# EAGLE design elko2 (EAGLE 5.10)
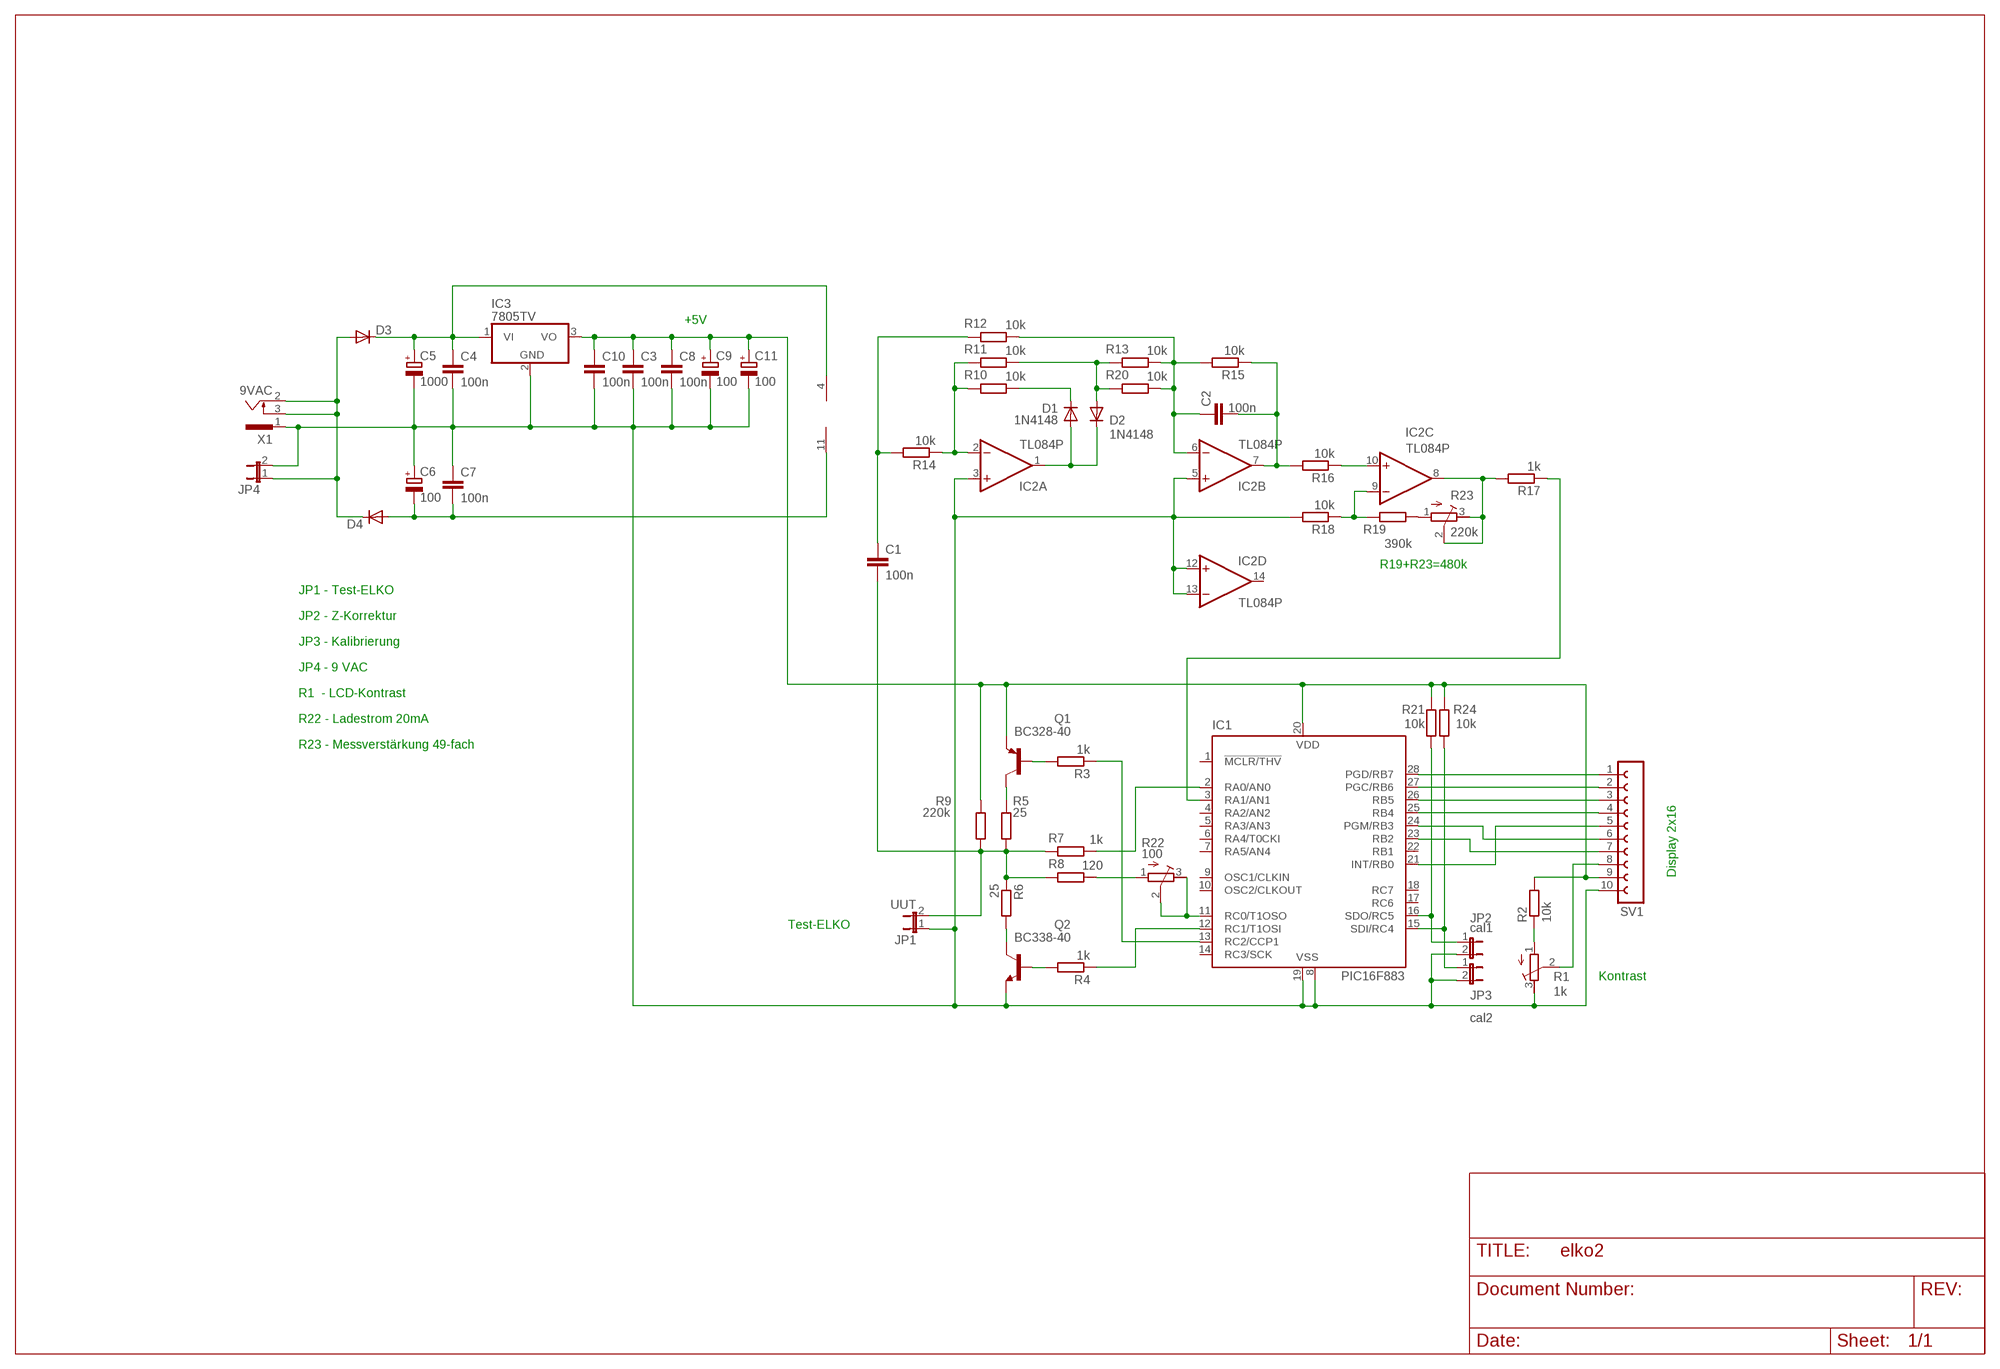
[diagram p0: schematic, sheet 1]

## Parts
C1  100n  C-EU050-025X075  [C050-025X075]
C2  100n  C-EU050-025X075  [C050-025X075]
C3  100n  C-EU050-025X075  [C050-025X075]
C4  100n  C-EU050-025X075  [C050-025X075]
C5  1000  CPOL-EUE5-8.5  [E5-8,5]
C6  100  CPOL-EUE5-6  [E5-6]
C7  100n  C-EU050-025X075  [C050-025X075]
C8  100n  C-EU050-025X075  [C050-025X075]
C9  100  CPOL-EUE5-6  [E5-6]
C10  100n  C-EU050-025X075  [C050-025X075]
C11  100  CPOL-EUE5-6  [E5-6]
D1  1N4148  1N4148DO35-7  [DO35-7]
D2  1N4148  1N4148DO35-7  [DO35-7]
D3  DIODE-DO15-12  [DO15-12]
D4  DIODE-DO15-12  [DO15-12]
IC1  PIC16F883  PIC16873P  [DIL28-3]
IC2  TL084P  [DIL14]
IC3  7805TV  [TO220V]
JP1  UUT  JP1E  [JP1]
JP2  cal1  JP1E  [JP1]
JP3  cal2  JP1E  [JP1]
JP4  JP1E  [JP1]
Q1  BC328-40  [TO92-EBC]
Q2  BC338-40  [TO92-EBC]
R1  1k  R-TRIMM3339P  [RTRIM3339P]
R2  10k  R-EU_0207/10  [0207/10]
R3  1k  R-EU_0207/10  [0207/10]
R4  1k  R-EU_0207/10  [0207/10]
R5  25  R-EU_0207/10  [0207/10]
R6  25  R-EU_0207/10  [0207/10]
R7  1k  R-EU_0207/10  [0207/10]
R8  120  R-EU_0207/10  [0207/10]
R9  220k  R-EU_0207/10  [0207/10]
R10  10k  R-EU_0207/10  [0207/10]
R11  10k  R-EU_0207/10  [0207/10]
R12  10k  R-EU_0207/10  [0207/10]
R13  10k  R-EU_0207/10  [0207/10]
R14  10k  R-EU_0207/10  [0207/10]
R15  10k  R-EU_0207/10  [0207/10]
R16  10k  R-EU_0207/10  [0207/10]
R17  1k  R-EU_0207/10  [0207/10]
R18  10k  R-EU_0207/10  [0207/10]
R19  390k  R-EU_0207/10  [0207/10]
R20  10k  R-EU_0207/10  [0207/10]
R21  10k  R-EU_0207/10  [0207/10]
R22  100  R-TRIMM64W  [RTRIM64W]
R23  220k  R-TRIMM64W  [RTRIM64W]
R24  10k  R-EU_0207/10  [0207/10]
SV1  FE10-1  [FE10]
X1  9VAC  733989-5  [733989-5]

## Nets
N$1: IC1.28(PGD/RB7) SV1.1
N$2: IC1.27(PGC/RB6) SV1.2
N$3: IC1.26(RB5) SV1.3
N$4: IC1.25(RB4) SV1.4
N$5: IC1.21(INT/RB0) SV1.5
N$6: IC1.24(PGM/RB3) SV1.6
N$7: IC1.23(RB2) SV1.7
N$8: R19.1 R23.1(E)
N$9: R8.1 R22.1(E)
N$10: C3.1 C8.1 C9.+ C10.1 C11.+ IC1.20(VDD) IC3.3(VO) Q1.E R2.2 R9.1 R21.2 R24.2 SV1.9
N$11: R1.2(S) SV1.8
N$12: C1.2 JP1.2 R5.2 R6.1 R7.2 R8.2 R9.2
N$13: IC1.2(RA0/AN0) R7.1
N$14: IC1.11(RC0/T1OSO) R22.2(S) R22.3(A)
N$15: Q1.C R5.1
N$16: Q1.B R3.2
N$17: Q2.B R4.2
N$18: IC1.12(RC1/T1OSI) R4.1
N$19: IC1.13(RC2/CCP1) R3.1
N$20: C4.1 C5.+ D3.C IC2.4(P:V+) IC3.1(VI)
N$21: IC2.2(A:-IN) R10.2 R11.2 R14.1
N$22: D1.A D2.C IC2.1(A:OUT)
N$23: R1.1(E) R2.1
N$24: D1.C R10.1
N$25: D2.A R11.1 R13.2 R20.2
N$26: C1.1 R12.2 R14.2
N$27: C2.1 IC2.6(B:-IN) R12.1 R13.1 R15.2 R20.1
N$28: IC1.16(SDO/RC5) JP2.1 R21.1
N$29: C2.2 IC2.7(B:OUT) R15.1 R16.2
N$30: IC2.10(C:+IN) R16.1
N$31: IC2.8(C:OUT) R17.2 R23.2(S) R23.3(A)
N$32: IC2.9(C:-IN) R18.1 R19.2
N$33: IC1.3(RA1/AN1) R17.1
N$34: Q2.C R6.2
N$35: IC1.15(SDI/RC4) JP3.1 R24.1
N$37: C6.- C7.2 D4.A IC2.11(P:V-)
N$38: D3.A D4.C JP4.1 X1.2 X1.3
VSS: C3.2 C4.2 C5.- C6.+ C7.1 C8.2 C9.- C10.2 C11.- IC1.8(VSS) IC1.19(VSS) IC2.3(A:+IN) IC2.5(B:+IN) IC2.12(D:+IN) IC2.13(D:-IN) IC3.2(GND) JP1.1 JP2.2 JP3.2 JP4.2 Q2.E R1.3(A) R18.2 SV1.10 X1.1
Unconnected: IC1.1(!MCLR/THV) IC1.4(RA2/AN2) IC1.5(RA3/AN3) IC1.6(RA4/T0CKI) IC1.7(RA5/AN4) IC1.9(OSC1/CLKIN) IC1.10(OSC2/CLKOUT) IC1.14(RC3/SCK) IC1.17(RC6) IC1.18(RC7) IC1.22(RB1) IC2.14(D:OUT)

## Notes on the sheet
- +5V
- R19+R23=480k
- JP1 - Test-ELKO
- JP2 - Z-Korrektur
- JP3 - Kalibrierung
- JP4 - 9 VAC
- R1  - LCD-Kontrast
- R22 - Ladestrom 20mA
- R23 - Messverstärkung 49-fach
- Display 2x16
- Test-ELKO
- Kontrast

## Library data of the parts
C1-C4 C7 C8 C10 = rcl:C-EU: CAPACITOR, European symbol
C5 C6 C9 C11 = rcl:CPOL-EU: POLARIZED CAPACITOR, European symbol
D1 D2 = diode:1N4148: DIODE
D3 D4 = diode:DIODE-: DIODE
IC1 = microchip-6:PIC16*873: MICROCONTROLLER flash type
IC2 = linear:TL084: OP AMP
IC3 = linear:78*: Positive VOLTAGE REGULATOR Source: http://cache.national.com/ds/LM/LM78L05.pdf http://www.fairchildsemi.com/ds/LM/LM7805.pdf
JP1-JP4 = jumper:JP1E: JUMPER
Q1 = transistor-pnp:BC328*: PNP Transistror
Q2 = transistor-npn:BC338*: NPN Transistor
R1 R22 R23 = rcl:R-TRIMM: Trimm resistor
R2-R21 R24 = rcl:R-EU_: RESISTOR, European symbol
SV1 = con-lsta:FE10-1: FEMALE HEADER
X1 = con-conrad:73398?: FEMALE PRINT CONNECTOR Niedervolt-Steckverbinder Distributor Conrad

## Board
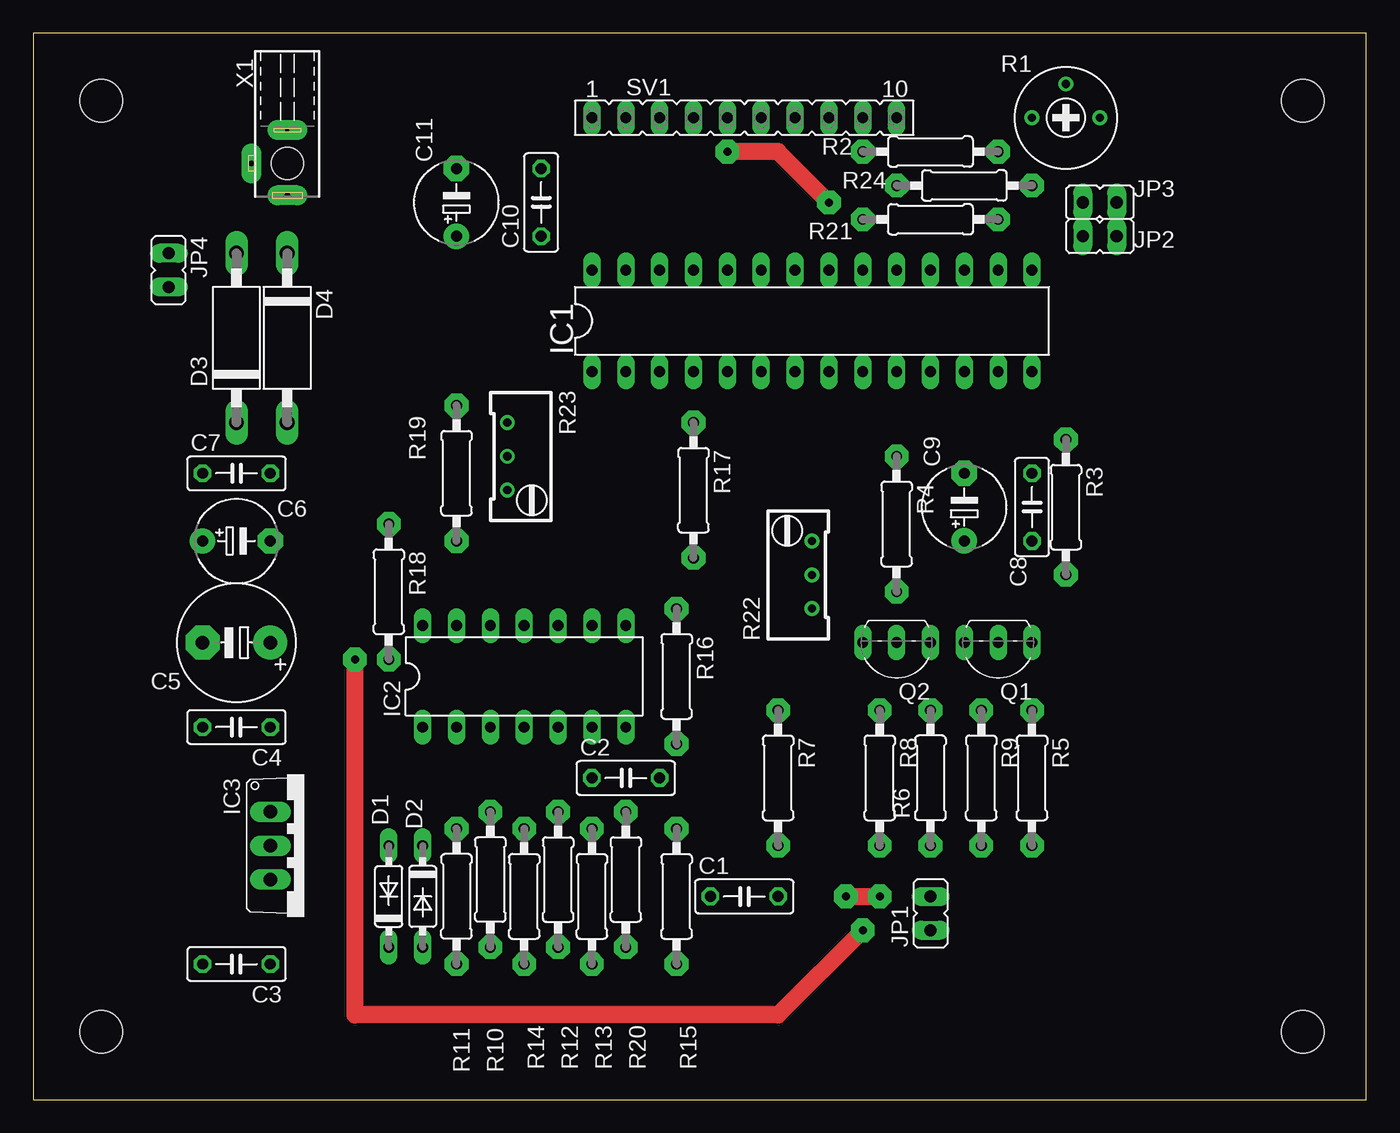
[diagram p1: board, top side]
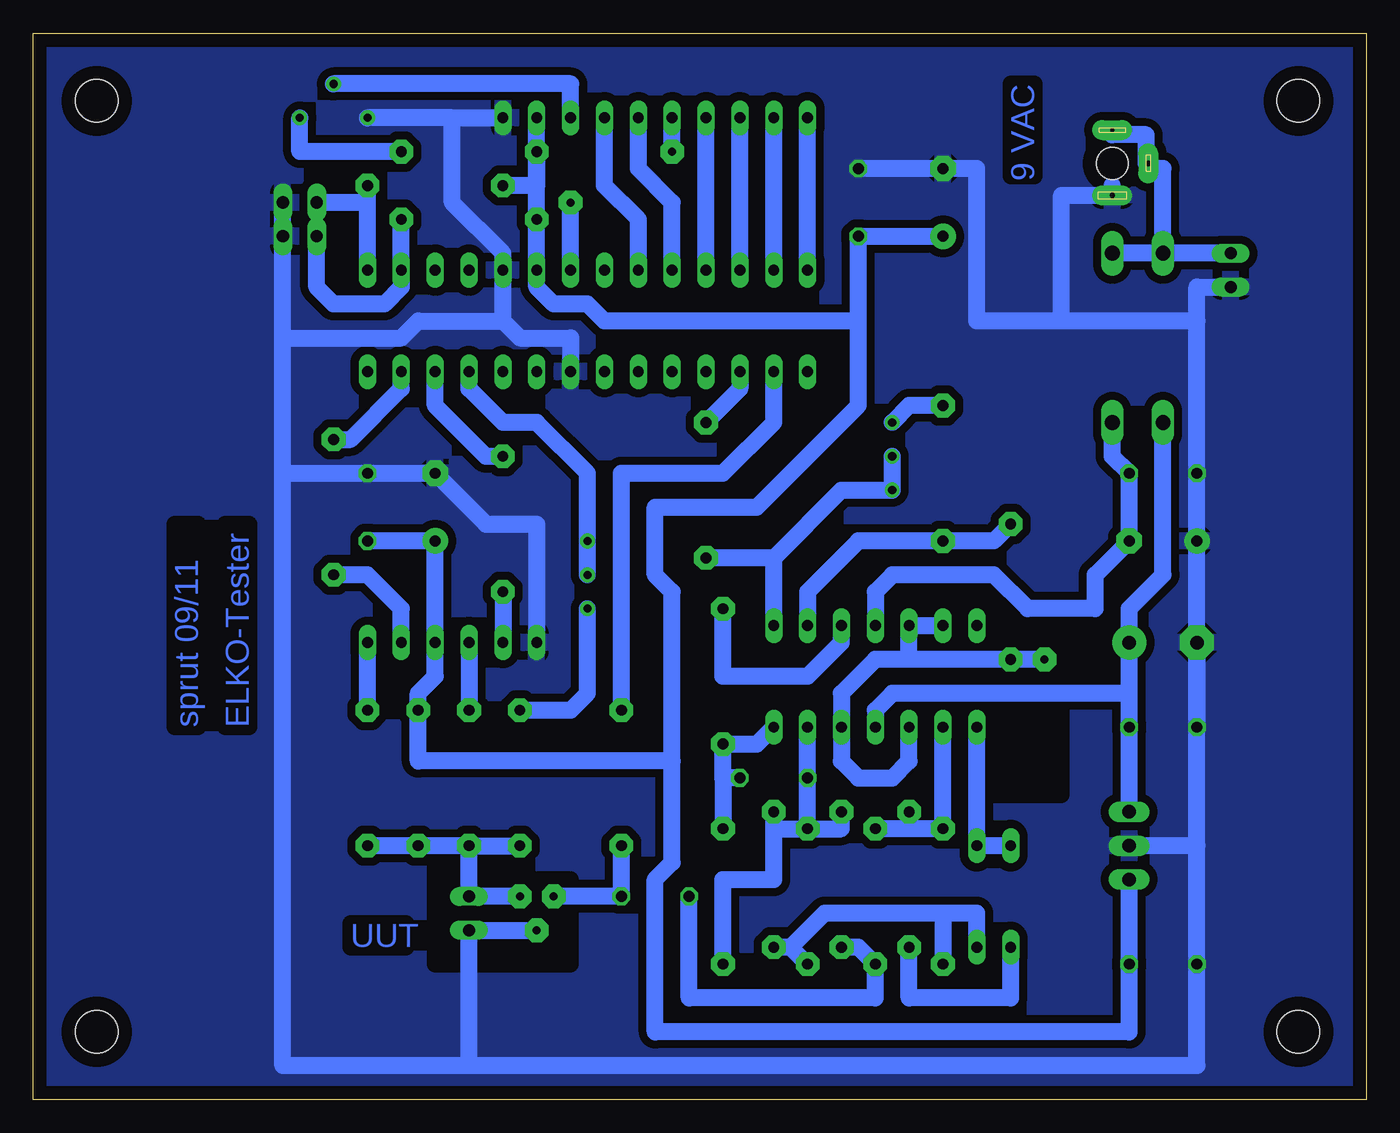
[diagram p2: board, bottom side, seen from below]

Size 100 x 80 mm. Coordinates in mm from the lower left corner, seen from the top.
Outline: 0,0 100,0 100,80 0,80 0,0
Copper layers (1*16): Top 0.035mm / dielectric 1.5mm / Bottom 0.035mm
Design rules "default": minimum track width 10mil, minimum drill 24mil, track to track 8mil, track to pad 8mil, pad to pad 8mil, via to via 8mil, smd to smd 8mil, copper to edge 40mil, drill to drill 8mil, minimum pad ring 10mil, minimum via ring 8mil, stop-mask expansion 4mil, vias tented up to drill 0mil, thermal gap 10mil
Holes 3.2 mm at 5.08,74.93 95.25,74.93 5.08,5.08 95.25,5.08
bRestrict: area 59.7,10.2 to 69.8,16.5; area 22.9,22.9 to 41.9,36.8

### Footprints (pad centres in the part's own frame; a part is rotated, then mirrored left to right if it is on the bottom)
C050-025X075 = drill 0.813 octagon: 1 -2.54,0; 2 2.54,0
E5-8,5 = drill 1.016 pad 2.54 round: + -2.54,0 | drill 1.016 pad 2.54 octagon: - 2.54,0
E5-6 = drill 0.813 pad 1.905 round: + -2.54,0 | drill 0.813 pad 1.905 octagon: - 2.54,0
DO35-7 = drill 0.813 long: A 3.81,0; C -3.81,0
DO15-12 = drill 1.118 long: A 6.35,0; C -6.35,0
DIL28-3 = drill 0.813 long: 1 -16.51,-3.81; 2 -13.97,-3.81; 3 -11.43,-3.81; 4 -8.89,-3.81; 5 -6.35,-3.81; 6 -3.81,-3.81; 7 -1.27,-3.81; 8 1.27,-3.81; 9 3.81,-3.81; 10 6.35,-3.81; 11 8.89,-3.81; 12 11.43,-3.81; 13 13.97,-3.81; 14 16.51,-3.81; 15 16.51,3.81; 16 13.97,3.81; 17 11.43,3.81; 18 8.89,3.81; 19 6.35,3.81; 20 3.81,3.81; 21 1.27,3.81; 22 -1.27,3.81; 23 -3.81,3.81; 24 -6.35,3.81; 25 -8.89,3.81; 26 -11.43,3.81; 27 -13.97,3.81; 28 -16.51,3.81
DIL14 = drill 0.813 long: 1 -7.62,-3.81; 2 -5.08,-3.81; 3 -2.54,-3.81; 4 0,-3.81; 5 2.54,-3.81; 6 5.08,-3.81; 7 7.62,-3.81; 8 7.62,3.81; 9 5.08,3.81; 10 2.54,3.81; 11 0,3.81; 12 -2.54,3.81; 13 -5.08,3.81; 14 -7.62,3.81
TO220V = drill 1.016 long: 1 -2.54,-2.54; 2 0,-2.54; 3 2.54,-2.54
JP1 = drill 0.914 long: 1 0,-1.27; 2 0,1.27
TO92-EBC = drill 0.813 long: B 0,-1.27; C -2.54,-1.27; E 2.54,-1.27
RTRIM3339P = drill 0.61 round: 1 -2.54,0; 2 0,-2.54; 3 2.54,0
0207/10 = drill 0.813 pad 1.778 octagon: 1 -5.08,0; 2 5.08,0
RTRIM64W = drill 0.61 round: 1 1.27,-2.54; 2 1.27,0; 3 1.27,2.54
FE10 = drill 0.813 long: 1 -11.43,0; 2 -8.89,0; 3 -6.35,0; 4 -3.81,0; 5 -1.27,0; 6 1.27,0; 7 3.81,0; 8 6.35,0; 9 8.89,0; 10 11.43,0
733989-5 = drill 0.4 pad 1.5 long: 1 0,5.82; 3 2.7,3.42 | drill 0.3 pad 1.5 long: 2 0,0.92 | hole 2.4: 0,3.42

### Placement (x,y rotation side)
C1  53.34,15.24 0 top
C2  44.45,24.13 0 top
C3  15.24,10.16 180 top
C4  15.24,27.94 180 top
C5  15.24,34.29 180 top
C6  15.24,41.91 0 top
C7  15.24,46.99 0 top
C8  74.93,44.45 90 top
C9  69.85,44.45 90 top
C10  38.1,67.31 90 top
C11  31.75,67.31 90 top
D1  26.67,15.24 90 top
D2  29.21,15.24 270 top
D3  15.24,57.15 90 top
D4  19.05,57.15 270 top
IC1  58.42,58.42 0 top
IC2  36.83,31.75 0 top
IC3  20.32,19.05 270 top
JP1  67.31,13.97 0 top
JP2  80.01,64.77 270 top
JP3  80.01,67.31 270 top
JP4  10.16,62.23 180 top
Q1  72.39,33.02 180 top
Q2  64.77,33.02 180 top
R1  77.47,73.66 180 top
R2  67.31,71.12 180 top
R3  77.47,44.45 270 top
R4  64.77,43.18 270 top
R5  74.93,24.13 270 top
R6  67.31,24.13 90 top
R7  55.88,24.13 270 top
R8  63.5,24.13 270 top
R9  71.12,24.13 270 top
R10  34.29,16.51 90 top
R11  31.75,15.24 90 top
R12  39.37,16.51 270 top
R13  41.91,15.24 270 top
R14  36.83,15.24 270 top
R15  48.26,15.24 270 top
R16  48.26,31.75 270 top
R17  49.53,45.72 270 top
R18  26.67,38.1 270 top
R19  31.75,46.99 270 top
R20  44.45,16.51 270 top
R21  67.31,66.04 180 top
R22  57.15,39.37 0 top
R23  36.83,48.26 180 top
R24  69.85,68.58 180 top
SV1  53.34,73.66 0 top
X1  19.05,73.66 180 top

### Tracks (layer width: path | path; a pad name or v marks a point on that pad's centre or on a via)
N$1
  Bottom 1.27: IC1.28 SV1.1
N$2
  Bottom 1.27: IC1.27 SV1.2
N$3
  Bottom 1.27: IC1.26 SV1.3
N$4
  Bottom 1.27: IC1.25 SV1.4
N$5  (via drill 0.6 pad 1.78)
  Top 1.27: v52.07,71.12 55.88,71.12 v59.69,67.31
  Bottom 1.27: v52.07,71.12 SV1.5 | IC1.21 v59.69,67.31
N$6
  Bottom 1.27: SV1.6 54.61,69.85 52.07,67.31 IC1.24
N$7
  Bottom 1.27: SV1.7 57.15,68.58 54.61,66.04 IC1.23
N$8
  Bottom 1.27: R19.1 34.29,52.07 R23.1
N$9
  Bottom 1.27: R8.1 59.69,29.21 58.42,30.48 R22.1
N$10
  Bottom 1.27: R2.2 SV1.9 | 52.07,25.4 71.12,25.4 R9.1 71.12,30.48 69.85,31.75 Q1.E C9.+ C8.1 | IC3.3 C3.1 17.78,5.08 53.34,5.08 53.34,16.51 52.07,17.78 52.07,25.4 | 38.1,58.42 57.15,58.42 58.42,59.69 60.96,59.69 62.23,60.96 IC1.20 R21.2 R2.2 | 38.1,58.42 38.1,52.07 45.72,44.45 53.34,44.45 53.34,39.37 52.07,38.1 52.07,25.4 | R2.2 62.23,68.58 R24.2 | 38.1,58.42 C10.1 C11.+
N$11
  Bottom 1.27: SV1.8 59.69,76.2 R1.2
N$12  (via drill 0.6 pad 1.78)
  Top 1.27: v60.96,15.24 v63.5,15.24
  Bottom 1.27: R6.1 R5.2 | R6.1 R9.2 | R6.1 JP1.2 v63.5,15.24 | R6.1 R8.2 | R7.2 C1.2 v60.96,15.24
N$13
  Bottom 1.27: IC1.2 44.45,50.8 48.26,46.99 55.88,46.99 R7.1
N$14
  Bottom 1.27: IC1.11 67.31,53.34 64.77,50.8 62.23,50.8 58.42,46.99 R22.3 R22.2
N$15
  Bottom 1.27: R5.1 Q1.C
N$16
  Bottom 1.27: R3.2 74.93,39.37 72.39,36.83 Q1.B
N$17
  Bottom 1.27: R4.2 Q2.B
N$18
  Bottom 1.27: IC1.12 69.85,52.07 66.04,48.26 R4.1
N$19
  Bottom 1.27: R3.1 76.2,49.53 72.39,53.34 IC1.13
N$20
  Bottom 1.27: D3.C 15.24,39.37 17.78,36.83 C5.+ C4.1 | IC3.1 C4.1 | C4.1 17.78,30.48 35.56,30.48 36.83,29.21 IC2.4
N$21
  Bottom 1.27: 34.29,20.32 R11.2 IC2.2 | 34.29,20.32 R14.1 | 34.29,20.32 R10.2
N$22
  Bottom 1.27: IC2.1 D2.C D1.A
N$23
  Bottom 1.27: R1.1 80.01,71.12 R2.1
N$24
  Bottom 1.27: R10.1 34.29,7.62 26.67,7.62 D1.C
N$25
  Bottom 1.27: 43.18,11.43 R20.2 | 43.18,11.43 R13.2 | D2.A 29.21,13.97 31.75,13.97 | 31.75,13.97 40.64,13.97 43.18,11.43 | 31.75,13.97 R11.1
N$26
  Bottom 1.27: R12.2 38.1,11.43 R14.2 36.83,7.62 50.8,7.62 C1.1
N$27
  Bottom 1.27: R12.1 39.37,20.32 R13.1 | 44.45,20.32 R13.1 | 44.45,20.32 R20.1 | IC2.6 C2.1 R13.1 | R15.2 48.26,16.51 44.45,16.51 44.45,20.32
N$28
  Bottom 1.27: R21.1 IC1.16 72.39,60.96 73.66,59.69 77.47,59.69 78.74,60.96 JP2.1
N$29
  Bottom 1.27: IC2.7 45.72,26.67 R16.2 48.26,24.13 | 48.26,24.13 R15.1 | C2.2 48.26,24.13
N$30
  Bottom 1.27: IC2.10 39.37,34.29 41.91,31.75 48.26,31.75 R16.1
N$31
  Bottom 1.27: IC2.8 44.45,40.64 | 44.45,40.64 R17.2 | R23.2 R23.3 39.37,45.72 44.45,40.64
N$32
  Bottom 1.27: IC2.9 41.91,38.1 38.1,41.91 R19.2 27.94,41.91 R18.1
N$33
  Bottom 1.27: R17.1 46.99,53.34 IC1.3
N$34
  Bottom 1.27: Q2.C R6.2
N$35
  Bottom 1.27: IC1.15 74.93,67.31 | 74.93,67.31 R24.1 | 74.93,67.31 JP3.1
N$37
  Bottom 1.27: D4.A 19.05,48.26 C7.2 C6.- 20.32,39.37 20.32,36.83 25.4,36.83 27.94,39.37 35.56,39.37 36.83,38.1 IC2.11
N$38
  Bottom 0.406: 16.35,69.85 X1.3 16.51,70.24
  Bottom 1.27: D3.A D4.C | D3.A 15.24,69.85 16.35,69.85 | 16.51,70.24 16.51,72.39 19.05,72.39 X1.2 | JP4.1 D3.A
VSS  (via drill 0.6 pad 1.78)
  Top 1.27: v24.13,33.02 24.13,6.35 55.88,6.35 v62.23,12.7
  Bottom 1.27: IC2.13 IC2.12 34.29,33.02 | 34.29,33.02 36.83,33.02 39.37,30.48 IC2.5 39.37,25.4 38.1,24.13 35.56,24.13 34.29,25.4 IC2.3 | 68.58,73.66 68.58,67.31 64.77,63.5 IC1.19 64.77,58.42 | 68.58,73.66 SV1.10 | 68.58,73.66 R1.3 | 12.7,19.05 C5.- C4.2 C6.+ C7.1 12.7,58.42 | 12.7,19.05 IC3.2 | 12.7,19.05 C3.2 12.7,2.54 67.31,2.54 | 67.31,2.54 81.28,2.54 81.28,46.99 | 81.28,46.99 C8.2 C9.- 66.04,43.18 62.23,43.18 Q2.E | 67.31,2.54 JP1.1 v62.23,12.7 | IC1.8 59.69,57.15 63.5,57.15 64.77,58.42 | 81.28,57.15 72.39,57.15 71.12,58.42 64.77,58.42 | 34.29,33.02 R18.2 v24.13,33.02 | 19.05,68.58 X1.1 22.86,67.84 22.86,58.42 | JP3.2 JP2.2 81.28,57.15 | 81.28,46.99 81.28,57.15 | C10.2 C11.- 29.21,69.85 29.21,58.42 22.86,58.42 | JP4.2 12.7,60.96 12.7,58.42 | 12.7,58.42 22.86,58.42
  pour Bottom (isolate 0.61): 0,81.28 101.6,81.28 101.6,-1.27 -1.27,-1.27 -1.27,81.28

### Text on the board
Bottom: 9 VAC | ELKO-Tester | sprut 09/11 | UUT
